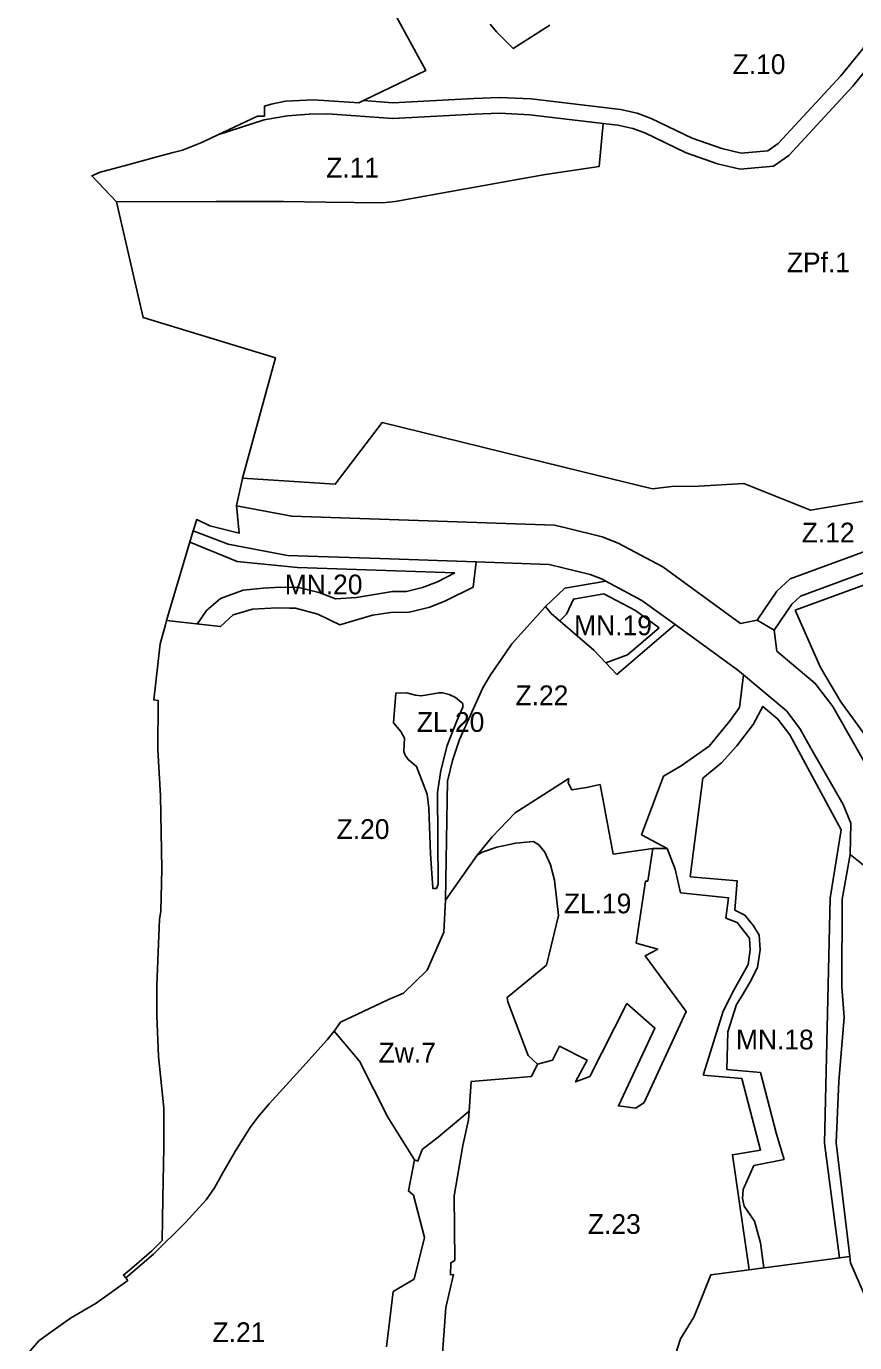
# Model space of a CAD drawing. Extents: x 7425478 to 7427982, y 5538517 to 5541171.
# Drawn here: x 7425690 to 7426110, y 5539161 to 5539827 of the extents above; entities that cross this region are included whole.
import ezdxf

# ---------------------------------------------------------------- set-up
doc = ezdxf.new("R2010")
doc.units = 0
for name, color, linetype in [('linie_rozgraniczajace', 7, 'Continuous'), ('linie_zabudowy_nieprzekraczalne', 7, 'Continuous'), ('oznaczenia_przeznaczen', 7, 'Continuous')]:
    doc.layers.add(name, color=color, linetype=linetype)

msp = doc.modelspace()

# ---------------------------------------------------------------- linework, layer by layer
at = {"layer": 'linie_rozgraniczajace'}
for p, q in [((7425953.48, 5539533.55), (7425963.17, 5539542.72)), ((7425989.5, 5539499.04), (7426019.03, 5539524.32)), ((7426060.68, 5539526.61), (7426069.33, 5539521.54)), ((7426053.69, 5539498.92), (7426050.89, 5539501.26)), ((7425918.82, 5539407.58), (7425902.81, 5539384.79)), ((7426007.81, 5539411.06), (7426015.07, 5539411.09)), ((7426117.82, 5539399.93), (7426107.74, 5539407.9)), ((7426056.56, 5539197.78), (7426107.49, 5539204.41))]:
    msp.add_line(p, q, dxfattribs=at)
for points in [[(7426172.93, 5539910.75), (7426157.78, 5539880.88), (7426131.38, 5539829.96), (7426120.78, 5539811.26), (7426109.12, 5539796.88), (7426076.6, 5539761.74), (7426068.87, 5539756.4), (7426052.03, 5539754.96), (7426040.49, 5539757.6), (7426024.63, 5539763.12), (7426003.8, 5539773.22), (7425997.61, 5539775.55), (7425990.1, 5539777.21), (7425982.57, 5539778.07)], [(7425861.28, 5539789.58), (7425876.14, 5539788.48), (7425917.05, 5539790.68), (7425930.12, 5539791.21), (7425946.2, 5539790.43), (7425991.44, 5539785.11), (7425999.89, 5539783.23), (7426006.95, 5539780.58), (7426027.7, 5539770.52), (7426042.71, 5539765.3), (7426052.59, 5539763.04), (7426066.07, 5539764.19), (7426071.32, 5539767.83), (7426103.07, 5539802.12), (7426114.14, 5539815.78), (7426124.35, 5539833.77), (7426150.65, 5539884.52), (7426159.34, 5539901.8)], [(7425690.44, 5539154.31), (7425696.83, 5539161.76), (7425701.62, 5539165.3), (7425712.74, 5539173.21), (7425725.77, 5539180.84), (7425741.84, 5539192.35), (7425740.8, 5539193.62), (7425739.6, 5539195.09), (7425745.02, 5539199.62), (7425753.96, 5539207.31), (7425759.27, 5539212.59), (7425759.67, 5539233.9), (7425760.15, 5539259.79), (7425760.18, 5539279.49), (7425757.37, 5539305.7), (7425756.58, 5539326.3), (7425756.49, 5539341.78), (7425757.97, 5539375.27), (7425758.57, 5539379.09), (7425759.09, 5539400.67), (7425758.49, 5539437.63), (7425757.06, 5539461.02), (7425757.21, 5539485.89), (7425755.01, 5539486.25), (7425758.25, 5539514.66), (7425760.9, 5539524.3), (7425761.48, 5539526.37), (7425763.57, 5539533.88), (7425775.02, 5539571.78), (7425776.74, 5539577.48), (7425783.32, 5539574.34), (7425798.28, 5539570.68), (7425796.89, 5539584.6), (7425799.89, 5539598.37), (7425799.91, 5539598.46), (7425816.66, 5539659.4), (7425749.58, 5539679.77), (7425736.06, 5539738.41), (7425723.58, 5539751.49), (7425727.82, 5539753.34), (7425732.47, 5539754.57), (7425741.87, 5539757.06), (7425757.29, 5539761.28), (7425764.81, 5539763.34), (7425769.57, 5539764.5), (7425778.77, 5539768.22), (7425780.08, 5539768.75), (7425787.4, 5539772.21), (7425807.54, 5539781.73), (7425811.02, 5539781.73), (7425811.08, 5539786.78), (7425814.45, 5539787.83), (7425821.76, 5539789.3), (7425835.89, 5539789.91), (7425853.98, 5539788.75), (7425858.87, 5539788.41), (7425861.28, 5539789.58), (7425892.77, 5539804.83), (7425875, 5539837.25)], [(7425925.41, 5539828.24), (7425928.56, 5539824.37), (7425937.12, 5539815.9), (7425955.69, 5539827.73)], [(7425982.57, 5539778.07), (7425945.54, 5539782.46), (7425930.09, 5539783.2), (7425917.43, 5539782.69), (7425876.06, 5539780.47), (7425843.19, 5539782.89), (7425833.78, 5539782.76), (7425822.77, 5539781.83), (7425810.9, 5539779.94), (7425787.4, 5539772.21)], [(7425736.06, 5539738.41), (7425786.58, 5539738.44), (7425820.78, 5539738.46), (7425842.18, 5539738.17), (7425870.91, 5539737.77), (7425877.26, 5539738.46), (7425940.03, 5539749.84), (7425953.36, 5539752.25), (7425980.59, 5539756.18), (7425982.57, 5539778.07)], [(7426069.33, 5539521.54), (7426078.15, 5539534.71), (7426082.62, 5539538.73), (7426164.84, 5539569.05), (7426330.34, 5539644.03), (7426343.82, 5539652.56), (7426397.35, 5539702.43)], [(7425799.91, 5539598.46), (7425846.93, 5539595.36), (7425870.72, 5539626.62), (7425972.37, 5539601.72)], [(7425972.37, 5539601.72), (7426007.65, 5539593.08), (7426017.26, 5539594.22), (7426031.17, 5539594.38), (7426053.91, 5539595.8)], [(7426053.91, 5539595.8), (7426087.71, 5539582.24), (7426116.53, 5539587.16), (7426144.44, 5539593.04), (7426169.45, 5539599.84)], [(7425796.9, 5539584.53), (7425824.93, 5539579.22), (7425958.05, 5539574.63), (7425964.38, 5539573.09)], [(7426172.52, 5539583.41), (7426161.08, 5539578.22), (7426077.37, 5539547.45), (7426070.54, 5539541.32), (7426060.68, 5539526.61)], [(7425775.02, 5539571.78), (7425792.66, 5539564.98), (7425822.74, 5539559.28), (7425869.52, 5539557.78), (7425918.29, 5539556.14)], [(7425964.38, 5539573.09), (7425982.12, 5539568.79), (7425990.22, 5539565.64), (7426012.81, 5539553.51), (7426026.05, 5539543.93)], [(7425916.72, 5539543.37), (7425918.29, 5539556.14)], [(7425918.29, 5539556.14), (7425955.32, 5539554.71), (7425976.12, 5539549.66), (7425981.84, 5539547.44), (7425984.05, 5539546.26)], [(7425761.48, 5539526.39), (7425788.84, 5539523.31), (7425795.24, 5539529.3), (7425805.04, 5539532.11), (7425817.47, 5539532.82), (7425823.7, 5539532.74), (7425826.83, 5539532.7), (7425838.08, 5539529.69), (7425849.18, 5539524.24), (7425865.75, 5539529.11), (7425875.01, 5539530.44), (7425884.44, 5539530.67), (7425886.53, 5539531.16), (7425894.87, 5539533.14), (7425902.83, 5539536.32), (7425916.72, 5539543.37)], [(7425984.05, 5539546.26), (7425963.17, 5539542.72)], [(7426019.03, 5539524.32), (7426002.17, 5539536.53), (7425984.05, 5539546.26)], [(7426060.68, 5539526.61), (7426052.24, 5539524.97), (7426026.05, 5539543.93)], [(7425953.48, 5539533.55), (7425936.44, 5539514.58), (7425931, 5539506.72), (7425925.56, 5539498.87), (7425921.76, 5539492.32), (7425909.83, 5539466.24), (7425906.36, 5539455.53), (7425903.86, 5539445.12), (7425903.54, 5539435.51), (7425902.81, 5539384.79)], [(7425953.48, 5539533.55), (7425956.37, 5539529.95), (7425977.93, 5539511.35), (7425983.9, 5539505), (7425989.5, 5539499.04)], [(7426050.89, 5539501.26), (7426019.03, 5539524.32)], [(7426070.57, 5539510.87), (7426069.33, 5539521.54)], [(7426070.57, 5539510.87), (7426090.07, 5539494.56), (7426098.94, 5539482.81), (7426122.19, 5539441.95)], [(7426053.69, 5539498.92), (7426051.61, 5539482.4), (7426047.01, 5539475.8), (7426036.31, 5539462.88), (7426022.16, 5539452.77), (7426013.16, 5539447.56), (7426001.99, 5539417.94)], [(7426053.69, 5539498.92), (7426075.49, 5539480.68), (7426082.2, 5539471.79), (7426087.86, 5539461.84)], [(7426087.86, 5539461.84), (7426104.14, 5539433.24), (7426108.01, 5539423.9), (7426107.74, 5539407.9)], [(7425918.82, 5539407.58), (7425926.44, 5539416.92), (7425938, 5539429), (7425965.32, 5539446.4)], [(7425965.32, 5539446.4), (7425964.84, 5539444.32), (7425966.8, 5539440.64), (7425974.19, 5539441.91), (7425981.11, 5539443.39), (7425987.73, 5539408.2), (7426007.81, 5539411.06)], [(7425949.35, 5539301.9), (7425944.63, 5539306.24), (7425934.41, 5539333.36), (7425934.03, 5539335.62), (7425953.96, 5539351.99), (7425959.99, 5539377.15), (7425958.02, 5539394.92), (7425955.96, 5539402.76), (7425953.08, 5539409.18), (7425950.12, 5539412.94), (7425947.3, 5539414.49), (7425938.37, 5539413.74), (7425928.7, 5539411.73), (7425921.27, 5539409.13), (7425918.82, 5539407.58)], [(7426001.99, 5539417.94), (7426015.07, 5539411.09)], [(7426007.81, 5539411.06), (7426005.23, 5539394.39)], [(7426015.07, 5539411.09), (7426019.18, 5539400.5), (7426021.75, 5539388.51)], [(7426107.49, 5539204.41), (7426100.73, 5539262.04), (7426102.06, 5539293), (7426104.67, 5539325.61), (7426103.6, 5539340.98), (7426103.69, 5539385.35), (7426107.74, 5539407.9)], [(7425999.26, 5539279.55), (7426003.32, 5539282.45), (7426024.72, 5539328.42), (7426003.86, 5539356.67), (7426010.3, 5539360.13), (7425999.37, 5539363.11), (7426004.14, 5539394.48), (7426005.23, 5539394.39)], [(7426021.75, 5539388.51), (7426046.12, 5539386.09), (7426044.72, 5539375.8)], [(7425846.31, 5539318.59), (7425849.6, 5539323.06), (7425869.98, 5539332.69), (7425873.61, 5539334.39), (7425881.57, 5539337.8), (7425893.56, 5539349.37), (7425899.03, 5539362.01), (7425901.89, 5539368.63), (7425902.81, 5539384.79)], [(7426044.72, 5539375.8), (7426050.51, 5539373.58), (7426056.78, 5539365.58), (7426057.11, 5539359.47), (7426056.03, 5539352.31), (7426048.75, 5539339.26), (7426043.38, 5539328.68), (7426034.47, 5539299.96), (7426033.33, 5539296.29)], [(7425949.35, 5539301.9), (7425956.95, 5539303.94), (7425960.53, 5539310.91), (7425974.49, 5539303.87), (7425968.65, 5539292.89), (7425975.85, 5539295.64), (7425994.68, 5539332.5), (7426008.82, 5539320.07), (7425990.34, 5539280.67), (7425999.26, 5539279.55)], [(7425740.8, 5539193.62), (7425754.92, 5539205.66), (7425771.25, 5539221.86), (7425781.51, 5539233.17), (7425785.69, 5539239.3), (7425789.93, 5539246.76), (7425796.43, 5539257.89), (7425803.91, 5539269.83), (7425807.74, 5539274.99), (7425813.38, 5539281.84), (7425829.05, 5539298.73), (7425842.76, 5539314.12), (7425846.31, 5539318.59)], [(7425887.14, 5539253.37), (7425873.57, 5539275.04), (7425859.22, 5539303.28), (7425846.31, 5539318.59)], [(7425949.35, 5539301.9), (7425946.27, 5539295.6), (7425915.69, 5539293.01), (7425914.83, 5539278)], [(7426033.33, 5539296.29), (7426052.84, 5539294.53), (7426062.36, 5539258.3), (7426048.12, 5539256), (7426056.56, 5539197.78)], [(7425887.14, 5539253.37), (7425888.82, 5539252.78), (7425890.87, 5539258.59), (7425898.99, 5539264.88), (7425914.83, 5539278)], [(7425911.14, 5539127.51), (7425895.48, 5539129.82), (7425894.29, 5539144.9), (7425900.95, 5539144.83), (7425900.94, 5539150.62), (7425903, 5539178.71), (7425906.76, 5539195.32), (7425905.22, 5539195.17), (7425905.53, 5539201.35), (7425907.43, 5539202.47), (7425907.2, 5539235.15), (7425911.58, 5539260.65), (7425914.39, 5539273.74), (7425914.83, 5539278)], [(7425872.91, 5539158.79), (7425876.32, 5539186.72), (7425886.84, 5539193.05), (7425892.12, 5539214.17), (7425886.62, 5539235.46), (7425884.02, 5539237.65), (7425887.14, 5539253.37)], [(7426019.32, 5539018.32), (7426129.7, 5539040.2), (7426134.42, 5539041.34), (7426137.76, 5539043.2), (7426141.67, 5539047.91), (7426142.89, 5539050.48), (7426143.53, 5539053.88), (7426141.59, 5539089.62), (7426135.87, 5539137), (7426107.86, 5539201.24), (7426107.49, 5539204.41)], [(7426015.22, 5539135.71), (7426018.42, 5539151.99), (7426020.29, 5539158.01), (7426021.79, 5539162.83), (7426028.53, 5539173.75), (7426030.01, 5539177.46), (7426037.1, 5539195.25), (7426056.56, 5539197.78)]]:
    msp.add_lwpolyline(points, dxfattribs=at)
msp.add_lwpolyline([(7425911.62, 5539482.6), (7425911.62, 5539484.33), (7425909.9, 5539485.78), (7425907.91, 5539487.46), (7425904.55, 5539488.95), (7425901.3, 5539489.86), (7425899.51, 5539489.89), (7425890.36, 5539488.22), (7425887.65, 5539488.69), (7425882.99, 5539489.86), (7425877.53, 5539489.63), (7425876.48, 5539474.67), (7425880.12, 5539470.15), (7425881.94, 5539466.86), (7425881.6, 5539460.13), (7425882.35, 5539458.17), (7425883.82, 5539456.01), (7425888.14, 5539452.57), (7425893.42, 5539438.52), (7425894.36, 5539431.36), (7425895.18, 5539408.36), (7425896.34, 5539391.04), (7425896.34, 5539390.78), (7425898.21, 5539390.82), (7425899.04, 5539392.95), (7425898.7, 5539439.42), (7425900.4, 5539450.49), (7425903.6, 5539463.22), (7425908.55, 5539475.7)], close=True, dxfattribs=at)
at = {"layer": 'linie_zabudowy_nieprzekraczalne'}
for p, q in [((7426079.94, 5539531.72), (7426092.64, 5539502.71)), ((7426045.8, 5539318.27), (7426045.26, 5539299.16))]:
    msp.add_line(p, q, dxfattribs=at)
for points in [[(7426415.67, 5539607.16), (7426407.47, 5539618.26), (7426398.09, 5539642.34), (7426399.86, 5539685.77), (7426388.87, 5539686.22), (7426347.5, 5539647.79), (7426333.19, 5539638.73), (7426167.12, 5539563.5), (7426079.94, 5539531.72)], [(7425907.42, 5539550.51), (7425827.86, 5539553.19), (7425797.22, 5539556.23), (7425772.86, 5539566.19)], [(7425777.05, 5539524.59), (7425781.76, 5539531.45), (7425788.83, 5539537.52), (7425800.33, 5539541.72), (7425810.48, 5539542.84), (7425819.11, 5539543.32), (7425828.48, 5539543.07), (7425839.3, 5539540.36), (7425847.06, 5539537.34), (7425857.72, 5539538.09), (7425875.89, 5539541.13), (7425883.08, 5539541.14), (7425891.08, 5539543.09), (7425898.67, 5539545.98), (7425907.42, 5539550.51)], [(7426011.02, 5539522.71), (7425998.97, 5539531.43), (7425983.03, 5539540), (7425967.56, 5539537.23), (7425963.99, 5539529.6), (7425960.69, 5539526.23)], [(7425983.9, 5539505), (7425995.04, 5539508.99), (7426011.02, 5539522.71)], [(7426092.64, 5539502.71), (7426103.07, 5539485.18), (7426140.12, 5539434.3), (7426151.92, 5539426.03), (7426171.4, 5539418.56), (7426334.52, 5539424.54)], [(7426077.18, 5539468.49), (7426071.11, 5539476.52), (7426063.57, 5539482.89), (7426058.65, 5539473.71), (7426050.36, 5539463.03), (7426042.65, 5539454.38), (7426033.15, 5539446.6), (7426026.63, 5539396.62)], [(7426102.28, 5539203.74), (7426094.72, 5539261.82), (7426097.69, 5539385.89), (7426103.21, 5539420.45), (7426077.18, 5539468.49)], [(7426026.63, 5539396.62), (7426050.57, 5539394.64), (7426049.37, 5539379.85), (7426054.39, 5539377.26), (7426058.78, 5539371.94), (7426061.7, 5539367.14), (7426062.1, 5539359.74), (7426060.82, 5539350.71), (7426057, 5539343.13), (7426053.01, 5539336.64), (7426050.11, 5539331.98), (7426045.8, 5539318.27)], [(7426045.26, 5539299.16), (7426062.28, 5539297.54), (7426070.44, 5539266.47), (7426074.23, 5539253.64), (7426058.88, 5539250.51)], [(7426058.88, 5539250.51), (7426053.57, 5539238.46), (7426053.26, 5539233.78), (7426054, 5539229.88), (7426059.27, 5539222.44), (7426062.3, 5539211.38), (7426063.95, 5539198.74)]]:
    msp.add_lwpolyline(points, dxfattribs=at)

# ---------------------------------------------------------------- texts
at = {"layer": 'oznaczenia_przeznaczen'}
for s, p in [('Z.10', (7426048.21, 5539803.03)), ('Z.11', (7425842.39, 5539750.66)), ('ZPf.1', (7426075.68, 5539702.69)), ('Z.12', (7426083.23, 5539565.94)), ('MN.20', (7425821.33, 5539539.66)), ('MN.19', (7425967.93, 5539518.96)), ('Z.22', (7425938.24, 5539483.55)), ('ZL.20', (7425888.26, 5539470.03)), ('Z.20', (7425847.64, 5539415.84)), ('ZL.19', (7425962.7, 5539378.19)), ('MN.18', (7426049.89, 5539309.28)), ('Zw.7', (7425868.9, 5539302.67)), ('Z.23', (7425974.92, 5539215.93)), ('Z.21', (7425784.81, 5539161.15))]:
    msp.add_text(s, height=10, dxfattribs=at).set_placement(p)

doc.saveas('drawing.dxf')
